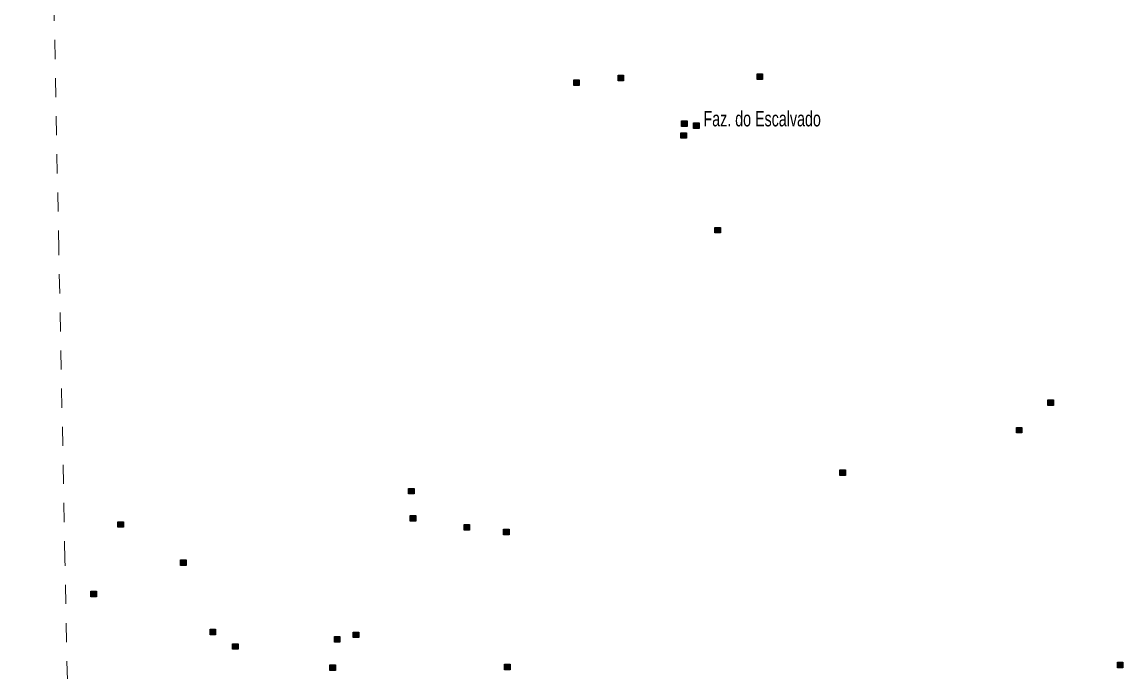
# Model space of a CAD drawing. Extents: x 220.8 to 246.7, y 7287.6 to 7315.8.
# Drawn here: x 220.75 to 226.53, y 7303.31 to 7306.72 of the extents above; entities that cross this region are included whole.
import ezdxf

# ---------------------------------------------------------------- set-up
doc = ezdxf.new("R2010")
doc.units = 0
doc.header["$LTSCALE"] = 0.032
doc.linetypes.add('SHORT_DASHED', pattern=[2.7, 1.5, -1.2])
doc.layers.add('2', color=7, linetype='Continuous', lineweight=25)
doc.layers.add('58', color=7, linetype='SHORT_DASHED', lineweight=13)
doc.layers.add('61', color=7, linetype='Continuous')

msp = doc.modelspace()

# ---------------------------------------------------------------- hatches: boundary and pattern name
at = {"layer": '2'}
for points in [[(223.6503, 7306.4186), (223.6793, 7306.4186), (223.6793, 7306.3896), (223.6503, 7306.3896)], [(223.8829, 7306.4429), (223.9119, 7306.4429), (223.9119, 7306.4139), (223.8829, 7306.4139)], [(224.612, 7306.4498), (224.641, 7306.4498), (224.641, 7306.4208), (224.612, 7306.4208)], [(224.2162, 7306.2033), (224.2452, 7306.2033), (224.2452, 7306.1743), (224.2162, 7306.1743)], [(224.2787, 7306.1929), (224.3077, 7306.1929), (224.3077, 7306.1639), (224.2787, 7306.1639)], [(224.2128, 7306.1408), (224.2418, 7306.1408), (224.2418, 7306.1118), (224.2128, 7306.1118)], [(224.391, 7305.6445), (224.42, 7305.6445), (224.42, 7305.6155), (224.391, 7305.6155)], [(226.1387, 7304.7391), (226.1677, 7304.7391), (226.1677, 7304.7101), (226.1387, 7304.7101)], [(225.9736, 7304.5948), (226.0026, 7304.5948), (226.0026, 7304.5658), (225.9736, 7304.5658)], [(225.0468, 7304.3715), (225.0758, 7304.3715), (225.0758, 7304.3425), (225.0468, 7304.3425)], [(222.7827, 7304.2747), (222.8117, 7304.2747), (222.8117, 7304.2457), (222.7827, 7304.2457)], [(221.2574, 7304.0999), (221.2864, 7304.0999), (221.2864, 7304.0709), (221.2574, 7304.0709)], [(222.792, 7304.132), (222.821, 7304.132), (222.821, 7304.103), (222.792, 7304.103)], [(223.0743, 7304.0854), (223.1033, 7304.0854), (223.1033, 7304.0564), (223.0743, 7304.0564)], [(223.2822, 7304.0606), (223.3112, 7304.0606), (223.3112, 7304.0316), (223.2822, 7304.0316)], [(221.5869, 7303.8998), (221.6159, 7303.8998), (221.6159, 7303.8708), (221.5869, 7303.8708)], [(221.1162, 7303.7351), (221.1452, 7303.7351), (221.1452, 7303.7061), (221.1162, 7303.7061)], [(221.7413, 7303.536), (221.7703, 7303.536), (221.7703, 7303.507), (221.7413, 7303.507)], [(222.4928, 7303.5207), (222.5218, 7303.5207), (222.5218, 7303.4917), (222.4928, 7303.4917)], [(221.8596, 7303.4597), (221.8886, 7303.4597), (221.8886, 7303.4307), (221.8596, 7303.4307)], [(222.3936, 7303.4978), (222.4226, 7303.4978), (222.4226, 7303.4688), (222.3936, 7303.4688)], [(222.3707, 7303.3491), (222.3997, 7303.3491), (222.3997, 7303.3201), (222.3707, 7303.3201)], [(223.2866, 7303.352), (223.3156, 7303.352), (223.3156, 7303.323), (223.2866, 7303.323)], [(226.5039, 7303.3623), (226.5329, 7303.3623), (226.5329, 7303.3333), (226.5039, 7303.3333)]]:
    msp.add_hatch(color=256, dxfattribs=at).paths.add_polyline_path(points)

# ---------------------------------------------------------------- linework, layer by layer
for points in [[(223.6503, 7306.4186), (223.6793, 7306.4186), (223.6793, 7306.3896), (223.6503, 7306.3896)], [(223.8829, 7306.4429), (223.9119, 7306.4429), (223.9119, 7306.4139), (223.8829, 7306.4139)], [(224.612, 7306.4498), (224.641, 7306.4498), (224.641, 7306.4208), (224.612, 7306.4208)], [(224.2162, 7306.2033), (224.2452, 7306.2033), (224.2452, 7306.1743), (224.2162, 7306.1743)], [(224.2787, 7306.1929), (224.3077, 7306.1929), (224.3077, 7306.1639), (224.2787, 7306.1639)], [(224.2128, 7306.1408), (224.2418, 7306.1408), (224.2418, 7306.1118), (224.2128, 7306.1118)], [(224.391, 7305.6445), (224.42, 7305.6445), (224.42, 7305.6155), (224.391, 7305.6155)], [(226.1387, 7304.7391), (226.1677, 7304.7391), (226.1677, 7304.7101), (226.1387, 7304.7101)], [(225.9736, 7304.5948), (226.0026, 7304.5948), (226.0026, 7304.5658), (225.9736, 7304.5658)], [(225.0468, 7304.3715), (225.0758, 7304.3715), (225.0758, 7304.3425), (225.0468, 7304.3425)], [(222.7827, 7304.2747), (222.8117, 7304.2747), (222.8117, 7304.2457), (222.7827, 7304.2457)], [(221.2574, 7304.0999), (221.2864, 7304.0999), (221.2864, 7304.0709), (221.2574, 7304.0709)], [(222.792, 7304.132), (222.821, 7304.132), (222.821, 7304.103), (222.792, 7304.103)], [(223.0743, 7304.0854), (223.1033, 7304.0854), (223.1033, 7304.0564), (223.0743, 7304.0564)], [(223.2822, 7304.0606), (223.3112, 7304.0606), (223.3112, 7304.0316), (223.2822, 7304.0316)], [(221.5869, 7303.8998), (221.6159, 7303.8998), (221.6159, 7303.8708), (221.5869, 7303.8708)], [(221.1162, 7303.7351), (221.1452, 7303.7351), (221.1452, 7303.7061), (221.1162, 7303.7061)], [(221.7413, 7303.536), (221.7703, 7303.536), (221.7703, 7303.507), (221.7413, 7303.507)], [(222.4928, 7303.5207), (222.5218, 7303.5207), (222.5218, 7303.4917), (222.4928, 7303.4917)], [(221.8596, 7303.4597), (221.8886, 7303.4597), (221.8886, 7303.4307), (221.8596, 7303.4307)], [(222.3936, 7303.4978), (222.4226, 7303.4978), (222.4226, 7303.4688), (222.3936, 7303.4688)], [(222.3707, 7303.3491), (222.3997, 7303.3491), (222.3997, 7303.3201), (222.3707, 7303.3201)], [(223.2866, 7303.352), (223.3156, 7303.352), (223.3156, 7303.323), (223.2866, 7303.323)], [(226.5039, 7303.3623), (226.5329, 7303.3623), (226.5329, 7303.3333), (226.5039, 7303.3333)]]:
    msp.add_lwpolyline(points, close=True, dxfattribs=at)
at = {"layer": '58'}
msp.add_lwpolyline([(221.3035, 7287.6034), (221.271, 7289.2329), (221.2386, 7290.8624), (221.2062, 7292.4919), (221.1738, 7294.1214), (221.1414, 7295.7509), (221.109, 7297.3804), (221.0767, 7299.0099), (221.0443, 7300.6394), (221.0121, 7302.2689), (220.9798, 7303.8984), (220.9475, 7305.5279), (220.9153, 7307.1574), (220.883, 7308.7869), (220.8508, 7310.4164), (220.8187, 7312.0459), (220.7865, 7313.6754), (220.7543, 7315.3049)], dxfattribs=at)

# ---------------------------------------------------------------- texts
at = {"layer": '61', "width": 0.7}
msp.add_text('Faz. do Escalvado', height=0.08, dxfattribs=at).set_placement((224.3311, 7306.1743))

doc.saveas('drawing.dxf')
